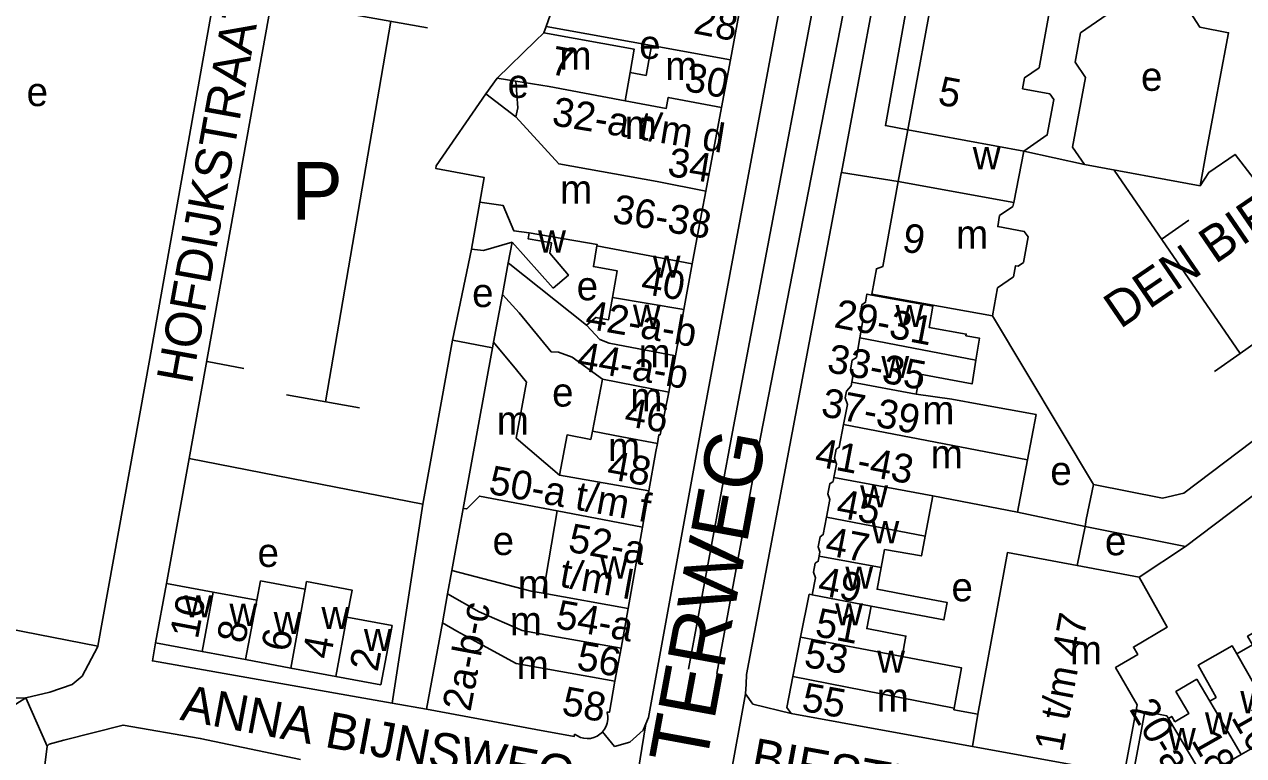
# Model space of a CAD drawing. Extents: x 161141 to 163125, y 381621 to 383200.
# Drawn here: x 161806 to 161975.3, y 381942 to 382043.6 of the extents above; entities that cross this region are included whole.
import ezdxf

# ---------------------------------------------------------------- set-up
doc = ezdxf.new("R2010")
doc.units = 0
for name, color, linetype in [('BLT_Basislijn', 7, 'Continuous'), ('BLT_Bebouwing', 7, 'Continuous'), ('BLT_Centroide', 7, 'Continuous'), ('BLT_Huisnummer', 7, 'Continuous'), ('BLT_Huisnummer_ tussenligend', 7, 'Continuous'), ('BLT_Huisnummer_reeks', 7, 'Continuous'), ('BLT_Onderdoorgang_en_onderverdeling', 7, 'Continuous'), ('BLT_Onderverdeling_panden', 7, 'Continuous'), ('BLT_Straatnaam', 7, 'Continuous'), ('BLT_Straatnaam_hoofdweg', 7, 'Continuous'), ('BLT_Tekst_parkeren', 7, 'Continuous'), ('BLT_Vlakafsluiter', 7, 'Continuous')]:
    doc.layers.add(name, color=color, linetype=linetype)

msp = doc.modelspace()

# ---------------------------------------------------------------- linework, layer by layer
at = {"layer": 'BLT_Basislijn'}
for p, q in [((161823.37, 381997.19), (161836.66, 382071.6)), ((161878.42, 382043.32), (161878.09, 382042.43)), ((161870.06, 382033.93), (161871.65, 382036.12)), ((161944.75, 382025.98), (161953.2, 382024.11)), ((161974.8, 381997.85), (161957.33, 382023.35)), ((161927.31, 382021.78), (161919.43, 382023)), ((161873.17, 382010.48), (161873.71, 382013.35)), ((161923.67, 382006.13), (161923.64, 382005.99)), ((161872.37, 382006.06), (161871.14, 381999.46)), ((161954.43, 381979.68), (161940.42, 382003.1)), ((161865.41, 381999.71), (161871, 381998.65)), ((161828.84, 381983.27), (161861.32, 381976.94)), ((161866.91, 381976.35), (161865.9, 381970.76)), ((161953.27, 381973.83), (161943.88, 381975.84)), ((161953.27, 381973.83), (161952.18, 381968.4)), ((161865.9, 381970.76), (161865.35, 381967.73)), ((161967.21, 381971.07), (161960.78, 381966.79)), ((161816.17, 381957.21), (161816.14, 381957.05)), ((161857.03, 381949.29), (161861.83, 381948.44))]:
    msp.add_line(p, q, dxfattribs=at)
for points in [[(161898.19, 381954.01), (161904.29, 381986.98), (161920.38, 382071.78), (161925.94, 382099.47)], [(161902.14, 381953.38), (161908.22, 381986.25), (161923.32, 382063.9), (161931.26, 382091.5)], [(161892.27, 381946.42), (161892.65, 381947.3), (161900, 381987.77), (161916.26, 382074.82)], [(161919.43, 382023), (161926.53, 382061.02)], [(161928.64, 382028.94), (161925.54, 382029.54), (161931, 382060.18)], [(161841.68, 382054.56), (161828.84, 381983.27)], [(161969.24, 382021.16), (161970.46, 382023.02), (161974.1, 382025.52), (161977.07, 382021.68)], [(161919.43, 382023), (161919.4, 382022.86), (161906.26, 381953.26), (161906.19, 381951.91)], [(161865.41, 381999.71), (161868.05, 382012.37)], [(161861.32, 381976.94), (161865.41, 381999.71)], [(161816.17, 381957.21), (161823.37, 381997.19)], [(161828.84, 381983.27), (161825.72, 381965.93)], [(161857.03, 381949.29), (161861.32, 381976.94)], [(161774.73, 381966.26), (161780.6, 381964.13), (161816.17, 381957.21)], [(161782.83, 381958.97), (161798.84, 381950.79), (161802.35, 381949.92), (161806.19, 381950)], [(161806.19, 381950), (161809.49, 381950.83), (161812.62, 381951.86), (161813.99, 381953.04), (161816.14, 381957.05)], [(161824.17, 381957.68), (161823.74, 381955.15), (161857.03, 381949.29)], [(161906.19, 381951.91), (161906.12, 381950.56)], [(161906.12, 381950.56), (161907.14, 381949.16), (161912.45, 381947.83)], [(161806.19, 381950), (161803.38, 381948.26), (161800.23, 381943.53), (161798.45, 381939.86)], [(161844.32, 381941.46), (161830.39, 381944.38), (161819.67, 381946.24), (161811.44, 381944.16), (161809.41, 381943.58), (161809.14, 381943.31)], [(161886.26, 381945.28), (161887.94, 381943.28), (161890.05, 381943.85), (161891.9, 381945.54), (161892.27, 381946.42)], [(161809.14, 381943.31), (161800.61, 381874.89), (161797.45, 381856.62), (161794.43, 381841.43)]]:
    msp.add_lwpolyline(points, dxfattribs=at)
at = {"layer": 'BLT_Bebouwing'}
for p, q in [((161905.69, 382047.54), (161904.02, 382038.65)), ((161878.42, 382043.32), (161893.08, 382040.67)), ((161904.02, 382038.65), (161902.78, 382032.06)), ((161874.21, 382035.71), (161871.65, 382036.12)), ((161863.17, 382023.93), (161870.06, 382033.93)), ((161870.06, 382033.93), (161874.24, 382030.73)), ((161902.78, 382032.06), (161900.6, 382020.43)), ((161928.64, 382028.94), (161927.31, 382021.78)), ((161944.75, 382025.98), (161943.36, 382018.84)), ((161953.2, 382024.11), (161969.24, 382021.16)), ((161879.4, 382006.94), (161873.71, 382013.35)), ((161872.37, 382006.06), (161873.17, 382010.48)), ((161873.17, 382010.48), (161884.03, 382001.78)), ((161898.71, 382010.34), (161897.56, 382003.98)), ((161896.38, 381997.55), (161897.56, 382003.98)), ((161871.14, 381999.46), (161871, 381998.65)), ((161871, 381998.65), (161866.91, 381976.35)), ((161895.45, 381992.51), (161896.38, 381997.55)), ((161886.24, 381994.32), (161884.87, 381987.07)), ((161934.78, 381991.5), (161938.82, 381990.76)), ((161884.87, 381987.07), (161884.66, 381985.92)), ((161892.71, 381978.8), (161893.66, 381984.23)), ((161893.66, 381984.23), (161893.88, 381985.38)), ((161891.79, 381973.73), (161892.71, 381978.8)), ((161879.97, 381976.01), (161878.02, 381964.56)), ((161889.83, 381962.44), (161891.79, 381973.73)), ((161967.21, 381971.07), (161953.27, 381973.83)), ((161864.75, 381964.46), (161865.35, 381967.73)), ((161952.18, 381968.4), (161960.78, 381966.79)), ((161824.17, 381957.68), (161825.72, 381965.93)), ((161864.02, 381960.46), (161864.75, 381964.46)), ((161914.95, 381964.42), (161913.77, 381958.44)), ((161915.39, 381964.34), (161914.95, 381964.42)), ((161888.83, 381956.91), (161889.83, 381962.44)), ((161861.83, 381948.44), (161864.02, 381960.46)), ((161857.03, 381960.06), (161855.48, 381951.81)), ((161830.66, 381956.47), (161824.17, 381957.68)), ((161913.77, 381958.44), (161912.7, 381952.97)), ((161836.7, 381955.34), (161830.66, 381956.47)), ((161842.96, 381954.16), (161836.7, 381955.34)), ((161888.83, 381956.91), (161887.99, 381952.32)), ((161849.22, 381952.99), (161842.96, 381954.16)), ((161855.48, 381951.81), (161849.22, 381952.99)), ((161968.79, 381952.6), (161970.59, 381949.56)), ((161877.01, 381945.64), (161861.83, 381948.44)), ((161912.45, 381947.83), (161926.17, 381945.33)), ((161886.25, 381945.27), (161886.26, 381945.28)), ((161926.17, 381945.33), (161937.63, 381943.24)), ((161980.47, 381945.31), (161974.95, 381942.17)), ((161937.63, 381943.24), (161958.7, 381939.4)), ((161974.95, 381942.17), (161969.67, 381939.05))]:
    msp.add_line(p, q, dxfattribs=at)
for points in [[(161928.64, 382028.94), (161932.58, 382050.37), (161934.36, 382060.03), (161935.91, 382059.74), (161937.22, 382060.65), (161939.06, 382070.6), (161943.26, 382073.49), (161953.27, 382071.65), (161953.91, 382072.09), (161954.31, 382074.25), (161985.54, 382068.51), (161989.77, 382062.38), (161989.52, 382061.05), (161994.29, 382054.12), (161994.07, 382052.96), (161996.64, 382052.49), (162001.39, 382045.56), (162000.94, 382042.94), (161999.99, 382042.3), (161999.61, 382042.01), (161999.02, 382038.85), (161999.99, 382037.45)], [(161880.54, 382051.6), (161879.55, 382046.47), (161878.42, 382043.32)], [(161948.29, 382045.21), (161946.88, 382037.56), (161944.88, 382036.18), (161944.59, 382034.65), (161948.38, 382033.96), (161948.93, 382033.15), (161948.03, 382028.24), (161944.75, 382025.98)], [(161969.24, 382021.16), (161970.14, 382026.07), (161971.2, 382031.76), (161971.86, 382035.29), (161973.2, 382042.43), (161969.19, 382043.21), (161967.86, 382045.3), (161962.26, 382046.3), (161960.21, 382044.89), (161957.08, 382045.47), (161952.63, 382042.41), (161951.88, 382038.33), (161953.33, 382036.22), (161951.54, 382026.52), (161953.2, 382024.11)], [(161876.97, 382041.32), (161878.09, 382042.43)], [(161890.09, 382036.92), (161890.67, 382040.14), (161878.09, 382042.43)], [(161871.65, 382036.12), (161876.97, 382041.32)], [(161893.08, 382040.67), (161892.3, 382036.5), (161890.09, 382036.92)], [(161874.24, 382030.73), (161874.49, 382031.99), (161874.21, 382035.71)], [(161869.2, 382018.89), (161869.82, 382022.33), (161863.13, 382023.57), (161863.17, 382023.93)], [(161927.31, 382021.78), (161925.17, 382009.95), (161924.3, 382009.64), (161923.67, 382006.13)], [(161900.6, 382020.43), (161900, 382017.29), (161898.71, 382010.34)], [(161868.05, 382012.37), (161869.2, 382018.89)], [(161940.42, 382003.1), (161941.12, 382006.98), (161943.34, 382008.52), (161943.62, 382010.06), (161943.99, 382009.99), (161944.74, 382010.51), (161945.38, 382014.07), (161944.84, 382014.84), (161941.14, 382015.51), (161941.41, 382017.02), (161943.26, 382018.3), (161943.36, 382018.84)], [(161876.09, 382014.63), (161875.94, 382013.78), (161879.18, 382013.22), (161878.93, 382011.81), (161881.53, 382008.74), (161879.4, 382006.94)], [(161885.48, 382012.81), (161885.52, 382013), (161876.09, 382014.63)], [(161873.71, 382013.35), (161869.73, 382012.16), (161868.05, 382012.37)], [(161887.64, 382005.64), (161888.29, 382009.37), (161884.99, 382009.94), (161885.48, 382012.81)], [(161923.67, 382006.13), (161940.42, 382003.1)], [(161886.24, 381994.32), (161882.03, 381997.36), (161880.14, 381998.06), (161879.12, 381998.12), (161874.69, 382003.53), (161872.37, 382006.06)], [(161884.03, 382001.78), (161885.35, 382002.88), (161887.11, 382002.56), (161887.64, 382005.64)], [(161921.99, 382000.02), (161922.43, 382002.45), (161922.07, 382003.44), (161922.29, 382004.64), (161922.79, 382004.99), (161922.99, 382006.11), (161923.64, 382005.99)], [(161923.64, 382005.99), (161932.15, 382004.45), (161931.61, 382001.49), (161936.77, 382000.56), (161936.73, 382000.34), (161938.61, 382000), (161938.12, 381996.95)], [(162000.69, 382003.92), (162000, 382003.4), (161995.47, 382000), (161966.98, 381978.47), (161964.04, 381977.78), (161954.43, 381979.68)], [(161880.28, 381980.98), (161874.29, 381986.1), (161875.68, 381993.88), (161874.3, 381995.58), (161871.14, 381999.46)], [(161921.99, 382000.02), (161921.51, 381997.32), (161920.95, 381996.94), (161920.7, 381995.6), (161921.02, 381994.68), (161920.87, 381993.9)], [(162004.34, 381999.08), (162000, 381995.81), (161967.21, 381971.07)], [(161929.84, 381992.2), (161930.37, 381995.01), (161937.59, 381993.63), (161938.12, 381996.95)], [(161920.87, 381993.9), (161920.77, 381993.37), (161920.13, 381992.63), (161919.96, 381991.72), (161920.28, 381990.8), (161919.74, 381987.99)], [(161893.88, 381985.38), (161894.09, 381986.58), (161894.25, 381986.55), (161895.45, 381992.51)], [(161929.84, 381992.2), (161934.78, 381991.5)], [(161938.82, 381990.76), (161946.48, 381989.37), (161945.27, 381983.1)], [(161919.74, 381987.99), (161919.14, 381984.85), (161918.69, 381984.55), (161918.46, 381983.33), (161918.75, 381982.51), (161918.39, 381980.64)], [(161884.66, 381985.92), (161881.33, 381986.55), (161880.28, 381980.98)], [(161945.27, 381983.1), (161943.88, 381975.84)], [(161918.39, 381980.64), (161918.29, 381980.09), (161917.82, 381979.77), (161917.55, 381978.38), (161917.84, 381977.57), (161917.37, 381975.11)], [(161953.27, 381973.83), (161953.45, 381974.78), (161954.43, 381979.68)], [(161866.91, 381976.35), (161867.4, 381976.26), (161869.16, 381978.05), (161879.97, 381976.01)], [(161932.14, 381978.09), (161931.08, 381972.49)], [(161943.88, 381975.84), (161932.14, 381978.09)], [(161917.37, 381975.11), (161916.91, 381972.7), (161916.49, 381972.41), (161916.22, 381971), (161916.46, 381970.31), (161916.34, 381969.7)], [(161931.08, 381972.49), (161930.55, 381969.74), (161925.44, 381970.63), (161924.96, 381968.12)], [(161916.34, 381969.7), (161916.21, 381968.99), (161915.8, 381968.72), (161915.57, 381967.48), (161915.84, 381966.7), (161915.39, 381964.34)], [(161952.18, 381968.4), (161942.5, 381970.21), (161938.4, 381947.73)], [(161865.35, 381967.73), (161876.35, 381964.86), (161878.02, 381964.56)], [(161924.96, 381968.12), (161924.39, 381965.11), (161929.46, 381964.15), (161934.14, 381963.25), (161933.68, 381960.84), (161923.55, 381962.78)], [(161825.72, 381965.93), (161832.2, 381964.72)], [(161838.24, 381963.58), (161838.78, 381966.26), (161844.97, 381965.1)], [(161844.97, 381965.1), (161845.17, 381966.17), (161851.47, 381964.99), (161850.77, 381961.24)], [(161958.7, 381939.4), (161959.63, 381944.37), (161960.51, 381949.07), (161957.51, 381954.23), (161960.58, 381956.05), (161959.98, 381957.07), (161964.68, 381959.85), (161960.78, 381966.79)], [(161832.2, 381964.72), (161838.24, 381963.58)], [(161927.86, 381955.75), (161928.4, 381958.61), (161922.95, 381959.65), (161923.55, 381962.78)], [(161850.77, 381961.24), (161857.03, 381960.06)], [(161974.34, 381956.12), (161976.54, 381957.37), (161975.85, 381958.58), (161978.42, 381960.04)], [(161970.59, 381949.56), (161971.48, 381950.09), (161968.96, 381954.54), (161973.71, 381957.23), (161974.34, 381956.12)], [(161935.09, 381948.57), (161936.11, 381954.21), (161927.86, 381955.75)], [(161887.99, 381952.32), (161887.21, 381948.02), (161886.86, 381948.05)], [(161912.7, 381952.97), (161911.87, 381948.7), (161912.45, 381947.83)], [(161968.79, 381952.6), (161965.9, 381950.89), (161967.7, 381947.85), (161965.76, 381946.7)], [(161938.4, 381947.73), (161935.05, 381948.36), (161935.09, 381948.57)], [(161886.26, 381945.28), (161886.54, 381945.65), (161886.77, 381946.07), (161886.92, 381946.52), (161886.99, 381946.99), (161886.98, 381947.46), (161886.89, 381947.93), (161886.86, 381948.05)], [(161964.88, 381947.14), (161964.61, 381947.54), (161961.58, 381948.1), (161960.84, 381944.13), (161959.91, 381939.18)], [(161965.76, 381946.7), (161965.32, 381947.45), (161964.88, 381947.14)], [(161882.38, 381944.99), (161882.33, 381944.65), (161877.01, 381945.64)], [(161882.38, 381944.99), (161882.77, 381944.72), (161883.2, 381944.52), (161883.66, 381944.4), (161884.14, 381944.35), (161884.61, 381944.39), (161885.07, 381944.5), (161885.51, 381944.69), (161885.9, 381944.95), (161886.25, 381945.27)]]:
    msp.add_lwpolyline(points, dxfattribs=at)
at = {"layer": 'BLT_Onderdoorgang_en_onderverdeling'}
for p, q in [((161944.75, 382025.98), (161928.64, 382028.94)), ((161943.36, 382018.84), (161927.31, 382021.78))]:
    msp.add_line(p, q, dxfattribs=at)
msp.add_lwpolyline([(161974.95, 381942.17), (161972.41, 381946.48), (161970.59, 381949.56)], dxfattribs=at)
at = {"layer": 'BLT_Onderverdeling_panden'}
for p, q in [((161847.8, 381991.16), (161856.84, 382044.04)), ((161851.78, 382044.94), (161861.94, 382043.13)), ((161893.08, 382040.67), (161904.02, 382038.65)), ((161889.42, 382032.98), (161890.09, 382036.92)), ((161963.96, 382013.78), (161967.68, 382016.41)), ((161885.48, 382012.81), (161898.71, 382010.34)), ((161887.64, 382005.64), (161897.56, 382003.98)), ((161884.03, 382001.78), (161885.9, 381999.83)), ((161887.2, 381999.32), (161885.9, 381999.83)), ((161938.12, 381996.95), (161921.99, 382000.02)), ((161974.8, 381997.85), (161978.92, 382000.8)), ((161887.2, 381999.32), (161896.38, 381997.55)), ((161974.8, 381997.85), (161971.27, 381995.35)), ((161831.35, 381996.74), (161836.44, 381995.78)), ((161886.24, 381994.32), (161895.45, 381992.51)), ((161929.84, 381992.2), (161920.87, 381993.9)), ((161842.36, 381992.12), (161852.52, 381990.31)), ((161945.27, 381983.1), (161919.74, 381987.99)), ((161932.14, 381978.09), (161918.39, 381980.64)), ((161879.97, 381976.01), (161891.79, 381973.73)), ((161931.08, 381972.49), (161917.37, 381975.11)), ((161924.96, 381968.12), (161916.34, 381969.7)), ((161830.66, 381956.47), (161832.2, 381964.72)), ((161842.96, 381954.16), (161844.97, 381965.1)), ((161878.02, 381964.56), (161889.83, 381962.44)), ((161923.55, 381962.78), (161915.39, 381964.34)), ((161836.7, 381955.34), (161838.24, 381963.58)), ((161849.22, 381952.99), (161850.77, 381961.24)), ((161888.83, 381956.91), (161879.36, 381958.61)), ((161927.86, 381955.75), (161913.77, 381958.44)), ((161974.34, 381956.12), (161980.47, 381945.31)), ((161935.09, 381948.57), (161912.7, 381952.97)), ((161938.4, 381947.73), (161937.63, 381943.24)), ((161964.88, 381947.14), (161969.67, 381939.05))]:
    msp.add_line(p, q, dxfattribs=at)
for points in [[(161874.21, 382035.71), (161878.84, 382034.96), (161889.42, 382032.98)], [(161889.42, 382032.98), (161895.11, 382031.91), (161895.4, 382033.45), (161902.78, 382032.06)], [(161874.24, 382030.73), (161880.17, 382024.21), (161893.83, 382021.78), (161900.6, 382020.43)], [(161869.2, 382018.89), (161872.47, 382018.43), (161873.93, 382014.93), (161876.09, 382014.63)], [(161893.88, 381985.38), (161888.96, 381986.3), (161884.87, 381987.07)], [(161880.28, 381980.98), (161892.71, 381978.8)], [(161864.75, 381964.46), (161869.15, 381961.97), (161875.11, 381959.37), (161879.36, 381958.61)], [(161864.02, 381960.46), (161866.01, 381959.29), (161867.06, 381958.71), (161874.29, 381954.78), (161887.99, 381952.32)]]:
    msp.add_lwpolyline(points, dxfattribs=at)
at = {"layer": 'BLT_Vlakafsluiter'}
for p, q in [((161906.12, 381950.56), (161903.29, 381935.24)), ((161809.14, 381943.31), (161806.19, 381950)), ((161892.27, 381946.42), (161889.41, 381928.6))]:
    msp.add_line(p, q, dxfattribs=at)

# ---------------------------------------------------------------- texts
at = {"layer": 'BLT_Centroide'}
for s, p in [('e', (161891.35, 382038.8)), ('m', (161880.28, 382037.29)), ('m', (161894.97, 382035.85)), ('e', (161961.04, 382034.36)), ('e', (161806.28, 382032.24)), ('e', (161873.07, 382033.38)), ('m', (161889.35, 382027.69)), ('w', (161937.68, 382023.47)), ('m', (161880.37, 382018.7)), ('w', (161877.31, 382011.89)), ('m', (161935.36, 382012.44)), ('w', (161893.23, 382008.41)), ('e', (161882.67, 382005.26)), ('e', (161868.15, 382004.32)), ('w', (161890.48, 382001.59)), ('w', (161926.95, 382001.53)), ('m', (161891.27, 381995.94)), ('w', (161924.98, 381994.46)), ('e', (161879.26, 381990.49)), ('m', (161890.12, 381989.84)), ('m', (161930.67, 381988.02)), ('m', (161871.58, 381986.59)), ('m', (161887.03, 381982.91)), ('m', (161931.84, 381981.91)), ('e', (161948.45, 381979.59)), ('w', (161922.04, 381976.47)), ('w', (161923.6, 381971.5)), ('e', (161870.99, 381969.86)), ('e', (161956.03, 381969.83)), ('e', (161838.35, 381968.21)), ('w', (161885.93, 381966.59)), ('w', (161919.98, 381965.19)), ('m', (161874.49, 381963.84)), ('e', (161934.72, 381963.43)), ('w', (161828.19, 381961.2)), ('w', (161834.45, 381960.02)), ('w', (161847.22, 381959.58)), ('w', (161918.56, 381960.09)), ('w', (161840.59, 381958.88)), ('m', (161873.39, 381958.72)), ('w', (161853.12, 381956.52)), ('m', (161951.16, 381954.69)), ('m', (161874.34, 381952.66)), ('w', (161924.4, 381953.5)), ('m', (161924.34, 381948.09)), ('w', (161974.83, 381947.89)), ('w', (161969.92, 381944.94)), ('w', (161964.8, 381942.77))]:
    msp.add_text(s, height=4, dxfattribs=at).set_placement(p)
at = {"layer": 'BLT_Huisnummer'}
for s, rotation, p in [('28', 348.9535, (161898.75, 382042.38)), ('7', 349.3352, (161878.87, 382036.72)), ('30', 349.3352, (161897.48, 382034.4)), ('9', 349.7596, (161927.7, 382012.11)), ('40', 350.195, (161891.44, 382006.23)), ('48', 349.6882, (161886.72, 381980.49)), ('45', 349.2105, (161918.57, 381975.16)), ('10', 79.3862, (161830.06, 381958.07)), ('51', 349.2105, (161915.62, 381958.62)), ('6', 79.3824, (161842.74, 381956.28)), ('2', 79.385, (161855.02, 381953.54)), ('55', 349.6728, (161913.76, 381948.25)), ('58', 349.527, (161880.45, 381947.72)), ('16', 299.5587, (161973.5, 381947.31)), ('18', 299.5587, (161967.95, 381944.12))]:
    msp.add_text(s, height=4, rotation=rotation, dxfattribs=at).set_placement(p)
at = {"layer": 'BLT_Huisnummer_ tussenligend'}
for s, rotation, p in [('46', 349.8852, (161889.14, 381987.86)), ('47', 349.2105, (161917.02, 381969.92)), ('49', 349.2105, (161916, 381964.37)), ('8', 79.3824, (161836.59, 381957.44)), ('4', 79.385, (161848.47, 381955.26)), ('56', 349.8389, (161882.52, 381953.97)), ('53', 349.2105, (161914.08, 381954.38))]:
    msp.add_text(s, height=4, rotation=rotation, dxfattribs=at).set_placement(p)
at = {"layer": 'BLT_Huisnummer_reeks'}
for s, rotation, p in [('5', 349.6091, (161932.68, 382032.49)), ('32-a t/m d', 350.7496, (161879.09, 382029.61)), ('34', 350.7496, (161895.14, 382022.57)), ('36-38', 350.1901, (161887.48, 382016.09)), ('42-a-b', 350.195, (161883.72, 382001.38)), ('29-31', 349.2046, (161918.28, 382001.54)), ('44-a-b', 349.8852, (161882.56, 381995.63)), ('33-35', 349.2078, (161917.29, 381995.32)), ('37-39', 349.2043, (161916.46, 381989.2)), ('41-43', 349.2015, (161915.57, 381982.26)), ('50-a t/m f', 349.7053, (161870.29, 381978.41)), ('52-a', 349.7053, (161881.34, 381970.36)), ('t/m l', 349.7053, (161880.15, 381965.5)), ('2a-b-c', 79.385, (161867.91, 381948)), ('54-a', 349.6876, (161879.59, 381959.74)), ('1 t/m 47', 79.4158, (161950.13, 381942.36)), ('20-a-b', 300.6555, (161959.34, 381948.45))]:
    msp.add_text(s, height=4, rotation=rotation, dxfattribs=at).set_placement(p)
at = {"layer": 'BLT_Straatnaam'}
for s, rotation, p in [('HOFDIJKSTRAAT', 79.7576, (161829.22, 381993.48)), ('DEN BIEST', 34.3282, (161958.16, 382001.21)), ('ANNA BIJNSWEG', 349.3929, (161827.45, 381946.99)), ('BIESTERDWARSWEG', 349.6535, (161906.66, 381939.55))]:
    msp.add_text(s, height=5, rotation=rotation, dxfattribs=at).set_placement(p)
at = {"layer": 'BLT_Straatnaam_hoofdweg'}
msp.add_text('AALSTERWEG', height=8, rotation=79.5414, dxfattribs=at).set_placement((161895.61, 381913.41))
at = {"layer": 'BLT_Tekst_parkeren'}
msp.add_text('P', height=8, dxfattribs=at).set_placement((161843.05, 382016.47))

doc.saveas('drawing.dxf')
